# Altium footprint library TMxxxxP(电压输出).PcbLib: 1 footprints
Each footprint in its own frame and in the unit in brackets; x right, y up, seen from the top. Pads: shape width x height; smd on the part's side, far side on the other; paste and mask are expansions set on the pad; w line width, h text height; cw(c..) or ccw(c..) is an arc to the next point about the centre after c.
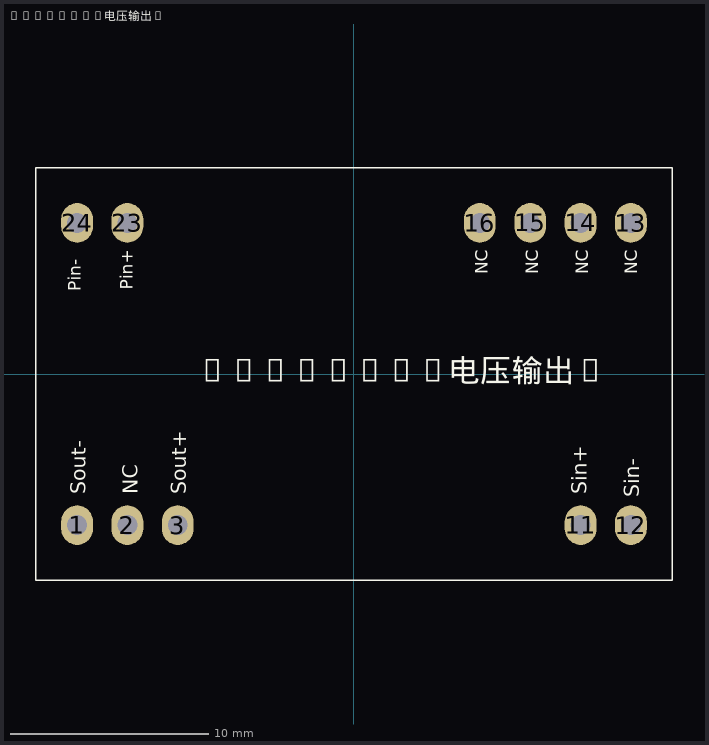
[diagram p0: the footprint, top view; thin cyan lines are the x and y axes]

## TMxxxxP(电压输出) [mm]
pads (11):
  oval 1.6x2 hole 1 mask+0.102: 1(-13.97,-7.62) 2(-11.43,-7.62) 3(-8.89,-7.62) 11(11.43,-7.62) 12(13.97,-7.62) 13(13.97,7.62) 14(11.43,7.62) 15(8.89,7.62) 16(6.35,7.62) 23(-11.43,7.62) 24(-13.97,7.62)
Top Overlay:
  lines w0.076: -16.05,-10.4 16.05,-10.4 16.05,10.4 -16.05,10.4 -16.05,-10.4
  text "NC" at 6.746,5.042 h0.64
  text "NC" at 9.286,5.042 h0.64
  text "Pin-" at -13.79,4.182 h0.64
  text "TMxxxxP(电压输出)" at -7.939,-0.787 h2
  text "Sin+" at 11.736,-6.067 h0.76
  text "NC" at 11.826,5.042 h0.64
  text "NC" at 14.299,5.042 h0.64
  text "Pin+" at -11.151,4.243 h0.64
  text "Sout-" at -13.533,-6.07 h0.76
  text "NC" at -10.898,-6.07 h0.76
  text "Sout+" at -8.453,-6.07 h0.76
  text "Sin-" at 14.382,-6.223 h0.76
